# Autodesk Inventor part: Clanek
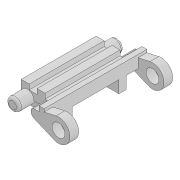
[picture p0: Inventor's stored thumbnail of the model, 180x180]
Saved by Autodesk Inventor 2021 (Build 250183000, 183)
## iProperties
Created: 2024-12
Part Number: Clanek
Material: Všeobecné
Document SubType Name: Modeling
Designer: tatulinek
Density: 1 g/cm^3
Appearance: Výchozí
Author: tatulinek
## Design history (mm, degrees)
sketch "Náčrt1"
  geometry: L1 (103.872, 237.697)-(260.522, 170.77); L2 (276.144, 339.021)-(184.14, 318.583); L3 (184.14, 318.583)-(184.14, 341.133); L4 (184.14, 341.133)-(145.64, 341.133); L5 (145.64, 341.133)-(145.64, 301.133); L6 (145.64, 301.133)-(101.89, 301.133); L7 (84.14, 283.383)-(84.14, 267.583); L8 (0, 411.919)-(0, -68.653) reference; L9 (-78.393, 0)-(470.358, 0) reference; C1 r 50 at (295.39, 252.383); A1 r 88.75 centre (295.39, 252.383) between (260.522, 170.77) and (276.144, 339.021); A2 r 17.75 centre (101.89, 283.383) between (101.89, 301.133) and (84.14, 283.383); A3 r 32.5 centre (116.64, 267.583) between (84.14, 267.583) and (103.872, 237.697); 1 further point
  constraints: 14 end point, 6 point on circle, 6 tangent, 4 centre point, 1 parallel, 1 perpendicular
  dimensions: "d0" = 88.75 radius of A1; "d1" = 100 diameter of C1; "d2" = 211.25 distance from line of C1.centre L7; "d4" = 88.75 distance from line of L4 C1.centre; "d5" = 22.55 distance of L2.end L3.end; "d6" = 40 distance of L4.end L5.end; "d7" = 61.5 distance between parallel lines of L7 L5; "d8" = 38.5 distance of L3.end L4.end; "d12" = 35.5 diameter of A2; "d13" = 31 vertical distance of C1.centre A2.centre; "d14" = 193.5 horizontal distance of C1.centre A2.centre; "d15" = 65 diameter of A3; "d16" = 15.8 vertical distance of A2.centre A3.centre
extrude "Boční pouzdro" new body sketch "Náčrt1" distance "d17" = 67.5; taper "d18" = 0 deg
node "Střed článku"
mirror "Zrcadlit1"
sketch "Náčrt2"
  geometry: L1 (-100.86, 341.133)-(-39.11, 341.133); L2 (-39.11, 301.133)-(22.39, 301.133); L3 (22.39, 341.133)-(84.14, 341.133); L4 (-39.11, 301.133)-(-39.11, 341.133); L5 (22.39, 301.133)-(22.39, 341.133); L6 (84.14, 341.133)-(84.14, 301.133); L7 (84.14, 301.133)-(145.64, 301.133); L8 (145.64, 301.133)-(145.64, 341.133); L9 (145.64, 341.133)-(184.14, 341.133); L10 (-100.86, 341.133)-(-100.86, 246.133); L11 (-100.86, 246.133)-(184.14, 246.133); L12 (184.14, 246.133)-(184.14, 341.133); L13 (184.14, 318.583)-(184.14, 341.133) reference; L14 (184.14, 341.133)-(145.64, 341.133) reference; 1 further point
  constraints: 24 end point, 5 equal length, 4 horizontal, 4 vertical, 2 parallel, 2 perpendicular, 1 collinear
  dimensions: "d20" = 61.75 distance of L1.start L1.end; "d21" = 61.5 distance of L2.start L2.end; "d22" = 40 distance of L2.start L1.end; "d23" = 38.5 distance of L9.end L8.end; "d24" = 95 distance of L1.start L10.end
extrude "Pás" join sketch "Náčrt2" stored distance "d25" = 580; taper "d26" = 0 deg
sketch "Náčrt3"
  geometry: L1 (276.144, 339.021)-(184.14, 318.583) reference; L2 (184.14, 318.583)-(184.14, 341.133) reference; L3 (184.14, 341.133)-(145.64, 341.133) reference; L4 (145.64, 341.133)-(145.64, 301.133) reference; L5 (145.64, 301.133)-(101.89, 301.133) reference; L6 (84.14, 283.383)-(84.14, 267.583) reference; L7 (103.872, 237.697)-(260.522, 170.77) reference; L8 (184.14, 246.133)-(184.14, 341.133) reference; L9 (-100.86, 246.133)-(184.14, 246.133) reference; C1 r 50 at (295.39, 252.383) reference; A1 r 88.75 centre (295.39, 252.383) between (260.522, 170.77) and (276.144, 339.021) reference; A2 r 17.75 centre (101.89, 283.383) between (101.89, 301.133) and (84.14, 283.383) reference; A3 r 32.5 centre (116.64, 267.583) between (84.14, 267.583) and (103.872, 237.697) reference; 2 further points
extrude "Dotažení pásu k bočnímu pouzdru" join sketch "Náčrt3" stored distance "d27" = 580; taper "d28" = 0 deg
mirror "Zrcadlit2"
node "Pro podélník na kterém je čep"
sketch "Náčrt4"
  geometry: L1 (-100.86, 246.133)-(184.14, 246.133); L2 (184.14, 246.133)-(184.14, 151.133); L3 (184.14, 151.133)-(-100.86, 151.133); L4 (-100.86, 151.133)-(-100.86, 246.133); L5 (-100.86, 246.133)-(92.224, 246.133) reference; 2 further points
  constraints: 8 end point, 2 parallel, 1 coincident, 1 collinear, 1 horizontal, 1 perpendicular, 1 point on line
  dimensions: "d30" = 95 distance of L3.end L1.start
extrude "Podélník" join sketch "Náčrt4" distance "d31" = 56.5; taper "d32" = 0 deg
sketch "Náčrt5"
  geometry: L1 (-100.86, 246.133)-(92.224, 246.133) reference; L2 (-100.86, 246.133)-(-100.86, 151.133) reference; C1 r 49 at (-51.86, 251.133); 1 further point
  constraints: 1 centre point, 1 tangent
  dimensions: "d33" = 98 diameter of C1; "d34" = 5 distance from line of L1 C1.centre
extrude "Čep" join sketch "Náčrt5" distance "d35" = 168; taper "d36" = 0 deg
fillet "Čep." dims "d37" = 20
mirror "Čep + podélník"
node "Těleso1"
node "Promítnutá smyčka1"
other parameters: "d29" = 181.25
